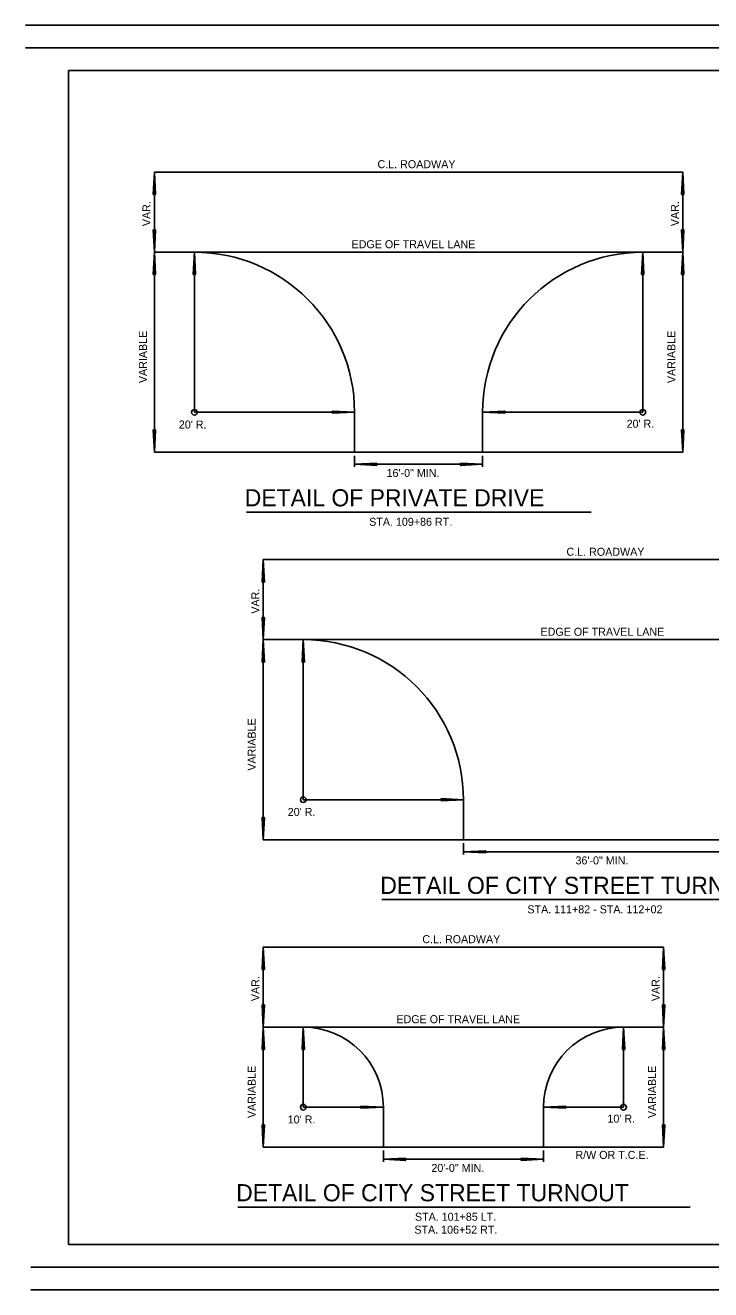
# Model space of a CAD drawing. Extents: x 1944905 to 1956777, y 763871 to 764977.
# Drawn here: x 1946613 to 1947213, y 763871 to 764977 of the extents above; entities that cross this region are included whole.
import ezdxf

# ---------------------------------------------------------------- set-up
doc = ezdxf.new("R2010")
doc.units = 0
doc.layers.add('Default', color=7, linetype='Continuous')
doc.layers.add('E_Existing ROW', color=7, linetype='Continuous')

msp = doc.modelspace()

# ---------------------------------------------------------------- linework, layer by layer
at = {"layer": 'Default'}
for p, q in [((1948232.1, 764976.7), (1946613.5, 764976.7)), ((1948232.1, 764957), (1946613.5, 764957)), ((1946651.2, 764937.3), (1948232.1, 764937.3)), ((1946651.2, 763910.1), (1946651.2, 764937.3)), ((1946726.3, 764848.2), (1946725.3, 764828.7)), ((1946726.3, 764848.2), (1947188.3, 764848.2)), ((1946726.3, 764778.2), (1946726.3, 764848.2)), ((1946727.3, 764828.7), (1946726.3, 764848.2)), ((1947188.3, 764848.2), (1947187.3, 764828.7)), ((1947188.3, 764778.2), (1947188.3, 764848.2)), ((1947189.3, 764828.7), (1947188.3, 764848.2)), ((1946725.3, 764828.7), (1946727.3, 764828.7)), ((1946727.3, 764828.6), (1946727.3, 764828.7)), ((1947187.3, 764828.7), (1947189.3, 764828.7)), ((1947189.3, 764828.6), (1947189.3, 764828.7)), ((1946725.3, 764797.9), (1946725.3, 764797.8)), ((1946725.3, 764797.8), (1946726.3, 764778.2)), ((1946727.3, 764797.8), (1946725.3, 764797.8)), ((1946726.3, 764778.2), (1946727.3, 764797.8)), ((1947187.3, 764797.9), (1947187.3, 764797.8)), ((1947187.3, 764797.8), (1947188.3, 764778.2)), ((1947189.3, 764797.8), (1947187.3, 764797.8)), ((1947188.3, 764778.2), (1947189.3, 764797.8)), ((1946726.3, 764778.2), (1946725.3, 764758.7)), ((1946727.3, 764758.7), (1946726.3, 764778.2)), ((1946726.3, 764603.2), (1946726.3, 764777.7)), ((1946760.3, 764758.7), (1946761.3, 764778.2)), ((1946761.3, 764778.2), (1947153.3, 764778.2)), ((1946761.3, 764778.2), (1946762.3, 764758.7)), ((1946761.3, 764778.2), (1946761.3, 764638.2)), ((1947153.3, 764778.2), (1947152.3, 764758.7)), ((1947154.3, 764758.7), (1947153.3, 764778.2)), ((1947153.3, 764778.2), (1947153.3, 764638.2)), ((1947188.3, 764778.2), (1947187.3, 764758.7)), ((1947189.3, 764758.7), (1947188.3, 764778.2)), ((1947188.3, 764603.2), (1947188.3, 764777.7)), ((1946725.3, 764758.7), (1946727.3, 764758.7)), ((1946727.3, 764758.6), (1946727.3, 764758.7)), ((1946762.3, 764758.7), (1946760.3, 764758.7)), ((1946760.3, 764758.6), (1946760.3, 764758.7)), ((1947152.3, 764758.7), (1947154.3, 764758.7)), ((1947154.3, 764758.6), (1947154.3, 764758.7)), ((1947187.3, 764758.7), (1947189.3, 764758.7)), ((1947189.3, 764758.6), (1947189.3, 764758.7)), ((1946881.7, 764639.2), (1946881.8, 764639.2)), ((1946881.8, 764639.2), (1946901.3, 764638.2)), ((1946881.8, 764637.3), (1946881.8, 764639.2)), ((1947032.8, 764639.2), (1947013.3, 764638.2)), ((1947032.8, 764637.3), (1947032.8, 764639.2)), ((1947032.9, 764639.2), (1947032.8, 764639.2)), ((1946761.3, 764638.2), (1946901.3, 764638.2)), ((1946901.3, 764638.2), (1946881.8, 764637.3)), ((1947153.3, 764638.2), (1947013.3, 764638.2)), ((1947013.3, 764638.2), (1947032.8, 764637.3)), ((1946725.3, 764622.9), (1946725.3, 764622.8)), ((1946725.3, 764622.8), (1946726.3, 764603.2)), ((1946727.3, 764622.8), (1946725.3, 764622.8)), ((1946726.3, 764603.2), (1946727.3, 764622.8)), ((1947187.3, 764622.9), (1947187.3, 764622.8)), ((1947187.3, 764622.8), (1947188.3, 764603.2)), ((1947189.3, 764622.8), (1947187.3, 764622.8)), ((1947188.3, 764603.2), (1947189.3, 764622.8)), ((1946901.3, 764603.2), (1946726.3, 764603.2)), ((1946901.3, 764603.2), (1947013.3, 764603.2)), ((1946901.3, 764600.2), (1946901.3, 764590.5)), ((1947188.3, 764603.2), (1947013.3, 764603.2)), ((1947013.3, 764600.2), (1947013.3, 764590.5)), ((1946920.8, 764593.7), (1946901.3, 764592.7)), ((1946901.3, 764592.7), (1946920.8, 764591.7)), ((1946901.3, 764592.7), (1947013.3, 764592.7)), ((1946920.8, 764591.7), (1946920.8, 764593.7)), ((1946920.9, 764593.7), (1946920.8, 764593.7)), ((1946993.7, 764591.7), (1946993.8, 764591.7)), ((1947013.3, 764592.7), (1946993.8, 764593.7)), ((1946993.8, 764593.7), (1946993.8, 764591.7)), ((1946993.8, 764591.7), (1947013.3, 764592.7)), ((1946806.8, 764550.9), (1947108.2, 764550.9)), ((1946821.5, 764509.3), (1946820.5, 764489.7)), ((1947423.5, 764509.3), (1946821.5, 764509.3)), ((1946821.5, 764439.3), (1946821.5, 764509.3)), ((1946822.5, 764489.7), (1946821.5, 764509.3)), ((1946820.5, 764489.7), (1946822.5, 764489.7)), ((1946822.5, 764489.7), (1946822.5, 764489.7)), ((1946820.5, 764458.9), (1946820.5, 764458.8)), ((1946820.5, 764458.8), (1946821.5, 764439.3)), ((1946822.5, 764458.8), (1946820.5, 764458.8)), ((1946821.5, 764439.3), (1946822.5, 764458.8)), ((1946821.5, 764439.3), (1946820.5, 764419.7)), ((1946822.5, 764419.7), (1946821.5, 764439.3)), ((1946821.5, 764264.3), (1946821.5, 764438.7)), ((1946855.5, 764419.7), (1946856.5, 764439.3)), ((1946856.5, 764439.3), (1947388.5, 764439.3)), ((1946856.5, 764439.3), (1946857.5, 764419.7)), ((1946856.5, 764439.3), (1946856.5, 764299.3)), ((1946820.5, 764419.7), (1946822.5, 764419.7)), ((1946822.5, 764419.7), (1946822.5, 764419.7)), ((1946857.5, 764419.7), (1946855.5, 764419.7)), ((1946855.5, 764419.7), (1946855.5, 764419.7)), ((1946856.5, 764299.3), (1946996.5, 764299.3)), ((1946976.9, 764300.3), (1946996.5, 764299.3)), ((1946976.9, 764298.3), (1946976.9, 764300.3)), ((1946976.9, 764300.3), (1946976.9, 764300.3)), ((1946996.5, 764299.3), (1946976.9, 764298.3)), ((1946820.5, 764283.9), (1946820.5, 764283.8)), ((1946820.5, 764283.8), (1946821.5, 764264.3)), ((1946822.5, 764283.8), (1946820.5, 764283.8)), ((1946821.5, 764264.3), (1946822.5, 764283.8)), ((1946996.5, 764264.3), (1946821.5, 764264.3)), ((1946996.5, 764264.3), (1947248.5, 764264.3)), ((1946996.5, 764261.3), (1946996.5, 764251.5)), ((1947016, 764254.7), (1946996.5, 764253.8)), ((1946996.5, 764253.8), (1947016, 764252.8)), ((1947248.5, 764253.8), (1946996.5, 764253.8)), ((1947016, 764252.8), (1947016, 764254.7)), ((1947016.1, 764254.7), (1947016, 764254.7)), ((1946925.3, 764211.9), (1947320.6, 764211.9)), ((1946820.5, 764150.8), (1946821.5, 764170.3)), ((1946821.5, 764170.3), (1947171.5, 764170.3)), ((1946821.5, 764100.3), (1946821.5, 764170.3)), ((1946821.5, 764170.3), (1946822.5, 764150.8)), ((1947170.5, 764150.8), (1947171.5, 764170.3)), ((1947171.5, 764100.3), (1947171.5, 764170.3)), ((1947171.5, 764170.3), (1947172.5, 764150.8)), ((1946822.5, 764150.8), (1946820.5, 764150.8)), ((1946820.5, 764150.7), (1946820.5, 764150.8)), ((1947172.5, 764150.8), (1947170.5, 764150.8)), ((1947170.5, 764150.7), (1947170.5, 764150.8)), ((1946821.5, 764100.3), (1946820.5, 764119.9)), ((1946820.5, 764119.9), (1946822.5, 764119.9)), ((1946822.5, 764119.9), (1946821.5, 764100.3)), ((1946822.5, 764120), (1946822.5, 764119.9)), ((1947171.5, 764100.3), (1947170.5, 764119.9)), ((1947170.5, 764119.9), (1947172.5, 764119.9)), ((1947172.5, 764119.9), (1947171.5, 764100.3)), ((1947172.5, 764120), (1947172.5, 764119.9)), ((1946820.5, 764080.8), (1946821.5, 764100.3)), ((1946821.5, 764100.3), (1946822.5, 764080.8)), ((1946821.5, 763995.3), (1946821.5, 764099.8)), ((1946855.5, 764080.8), (1946856.5, 764100.3)), ((1946856.5, 764100.3), (1947136.5, 764100.3)), ((1946856.5, 764100.3), (1946857.5, 764080.8)), ((1946856.5, 764100.3), (1946856.5, 764030.3)), ((1947135.5, 764080.8), (1947136.5, 764100.3)), ((1947136.5, 764100.3), (1947136.5, 764030.3)), ((1947136.5, 764100.3), (1947137.5, 764080.8)), ((1947170.5, 764080.8), (1947171.5, 764100.3)), ((1947171.5, 764100.3), (1947172.5, 764080.8)), ((1947171.5, 763995.3), (1947171.5, 764099.8)), ((1946822.5, 764080.8), (1946820.5, 764080.8)), ((1946820.5, 764080.7), (1946820.5, 764080.8)), ((1946857.5, 764080.8), (1946855.5, 764080.8)), ((1946855.5, 764080.7), (1946855.5, 764080.8)), ((1947137.5, 764080.8), (1947135.5, 764080.8)), ((1947135.5, 764080.7), (1947135.5, 764080.8)), ((1947172.5, 764080.8), (1947170.5, 764080.8)), ((1947170.5, 764080.7), (1947170.5, 764080.8)), ((1946856.5, 764030.3), (1946926.5, 764030.3)), ((1946906.9, 764031.3), (1946926.5, 764030.3)), ((1946906.9, 764029.4), (1946906.9, 764031.3)), ((1946906.9, 764031.3), (1946906.9, 764031.3)), ((1946926.5, 764030.3), (1946906.9, 764029.4)), ((1947066.5, 764030.3), (1947086, 764031.3)), ((1947066.5, 764030.3), (1947136.5, 764030.3)), ((1947086, 764029.4), (1947066.5, 764030.3)), ((1947086, 764031.3), (1947086, 764029.4)), ((1947086.1, 764029.4), (1947086, 764029.4)), ((1946821.5, 763995.3), (1946820.5, 764014.9)), ((1946820.5, 764014.9), (1946822.5, 764014.9)), ((1946822.5, 764014.9), (1946821.5, 763995.3)), ((1946822.5, 764015), (1946822.5, 764014.9)), ((1947171.5, 763995.3), (1947170.5, 764014.9)), ((1947170.5, 764014.9), (1947172.5, 764014.9)), ((1947172.5, 764014.9), (1947171.5, 763995.3)), ((1947172.5, 764015), (1947172.5, 764014.9)), ((1946821.5, 763995.3), (1946926.5, 763995.3)), ((1946926.5, 763995.3), (1947066.5, 763995.3)), ((1946926.5, 763992.3), (1946926.5, 763982.6)), ((1947066.5, 763995.3), (1947171.5, 763995.3)), ((1947066.5, 763992.3), (1947066.5, 763982.6)), ((1946926.5, 763984.8), (1946946, 763985.8)), ((1946946, 763983.8), (1946926.5, 763984.8)), ((1946926.5, 763984.8), (1947066.5, 763984.8)), ((1946946, 763985.8), (1946946, 763983.8)), ((1946946.1, 763983.8), (1946946, 763983.8)), ((1947046.9, 763985.8), (1947066.5, 763984.8)), ((1947046.9, 763983.8), (1947046.9, 763985.8)), ((1947046.9, 763985.8), (1947046.9, 763985.8)), ((1947066.5, 763984.8), (1947046.9, 763983.8)), ((1946799.3, 763943), (1947194.6, 763943)), ((1948232.1, 763910.1), (1946651.2, 763910.1)), ((1946618.4, 763890.4), (1948232.1, 763890.4)), ((1946618.4, 763870.7), (1948232.1, 763870.7))]:
    msp.add_line(p, q, dxfattribs=at)
for centre in [(1946761.3, 764638.2), (1947153.3, 764638.2), (1946856.5, 764299.3), (1946856.5, 764030.3), (1947136.5, 764030.3)]:
    msp.add_circle(centre, 2.44, dxfattribs=at)
at = {"layer": 'E_Existing ROW'}
for p, q in [((1946726.3, 764778.2), (1946761.3, 764778.2)), ((1947153.3, 764778.2), (1947188.3, 764778.2)), ((1946901.3, 764638.2), (1946901.3, 764603.2)), ((1947013.3, 764638.2), (1947013.3, 764603.2)), ((1946821.5, 764439.3), (1946856.5, 764439.3)), ((1946996.5, 764299.3), (1946996.5, 764264.3)), ((1946821.5, 764100.3), (1946856.5, 764100.3)), ((1947136.5, 764100.3), (1947171.5, 764100.3)), ((1946926.5, 764030.3), (1946926.5, 763995.3)), ((1947066.5, 764030.3), (1947066.5, 763995.3))]:
    msp.add_line(p, q, dxfattribs=at)
for centre, radius, start, end in [((1946761.3, 764638.2), 140, 0, 90), ((1947153.3, 764638.2), 140, 90, 180), ((1946856.5, 764299.3), 140, 0, 90), ((1946856.5, 764030.3), 70, 0, 90), ((1947136.5, 764030.3), 70, 90, 180)]:
    msp.add_arc(centre, radius, start, end, dxfattribs=at)

# ---------------------------------------------------------------- texts
at = {"layer": 'Default'}
for s, height, p in [('C.L. ROADWAY', 7, (1946921.4, 764851.7)), ('EDGE OF TRAVEL LANE', 7, (1946898.7, 764781.7)), ("20' R.", 7, (1946747.7, 764624)), ("20' R.", 7, (1947139.2, 764624.7)), ('16\'-0" MIN.', 7, (1946929.3, 764581.6)), ('DETAIL OF PRIVATE DRIVE', 15, (1946805.3, 764555.9)), ('STA. 109+86 RT.', 7, (1946914.1, 764538.9)), ('C.L. ROADWAY', 7, (1947086.6, 764512.7)), ('EDGE OF TRAVEL LANE', 7, (1947063.9, 764442.7)), ("20' R.", 7, (1946842.9, 764285.1)), ('36\'-0" MIN.', 7, (1947094.5, 764242.7)), ('DETAIL OF CITY STREET TURNOUT', 15, (1946923.8, 764216.9)), ('STA. 111+82 - STA. 112+02', 7, (1947052.4, 764199.9)), ('C.L. ROADWAY', 7, (1946960.6, 764173.8)), ('EDGE OF TRAVEL LANE', 7, (1946937.9, 764103.8)), ("10' R.", 7, (1946842.9, 764016.1)), ("10' R.", 7, (1947122.4, 764016.8)), ('R/W OR T.C.E.', 7, (1947094.4, 763985.1)), ('20\'-0" MIN.', 7, (1946968.5, 763973.7)), ('DETAIL OF CITY STREET TURNOUT', 15, (1946797.8, 763948)), ('STA. 101+85 LT.', 7, (1946954.1, 763931)), ('STA. 106+52 RT.', 7, (1946953.6, 763919.7))]:
    msp.add_text(s, height=height, dxfattribs=at).set_placement(p)
for s, p in [('VAR.', (1946722.9, 764801)), ('VAR.', (1947184.9, 764801)), ('VARIABLE', (1946719.8, 764663.7)), ('VARIABLE', (1947181.8, 764663.7)), ('VAR.', (1946818.1, 764462)), ('VARIABLE', (1946814.9, 764324.7)), ('VAR.', (1946818.1, 764123.1)), ('VAR.', (1947168.1, 764123.1)), ('VARIABLE', (1946814.9, 764020.8)), ('VARIABLE', (1947164.9, 764020.8))]:
    msp.add_text(s, height=7, rotation=90, dxfattribs=at).set_placement(p)

doc.saveas('drawing.dxf')
